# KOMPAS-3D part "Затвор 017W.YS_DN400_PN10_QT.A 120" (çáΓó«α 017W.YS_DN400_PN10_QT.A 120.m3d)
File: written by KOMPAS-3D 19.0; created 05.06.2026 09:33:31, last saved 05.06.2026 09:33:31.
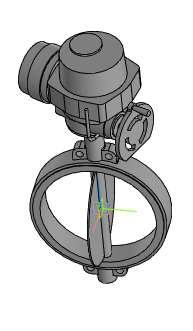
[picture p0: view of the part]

Document properties: Автор: Энергия; Полное имя файла: ..\..\..\3d для проектировщиков\x.x Тип 017W.Y(S) Затвор дисковый поворотный межфланцевый\Затвор 017W.Y(S)_DN32-DN450_QT.Z\Затвор 017W.YS_DN400_PN10_QT.A 120.a3d

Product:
- Part/product: Затвор 017W.YS_DN400_PN10_QT.A 120
    Масса: 191.123

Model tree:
1. Операция без истории:1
